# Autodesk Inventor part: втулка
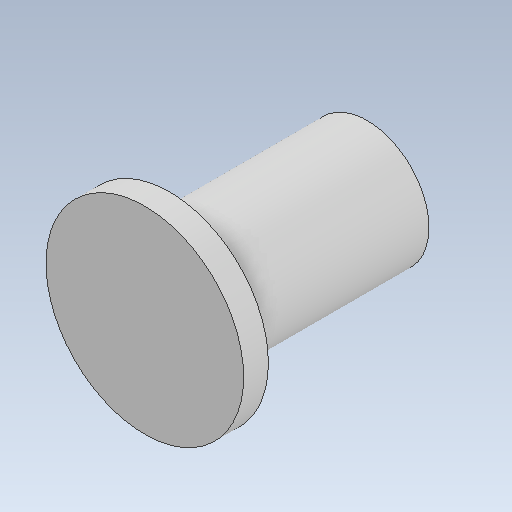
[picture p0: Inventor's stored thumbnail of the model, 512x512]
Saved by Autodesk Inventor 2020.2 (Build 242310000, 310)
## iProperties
Created: 2020-04
Part Number: втулка
Material: Типовые
Document SubType Name: Modeling
Designer: Алексей
Density: 1 g/cm^3
Appearance: По умолчанию
Author: Алексей
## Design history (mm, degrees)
sketch "Эскиз1"
  geometry: C1 r 2.5 at (-8.843, 5.951) reference; C2 r 2.5 at (-8.843, 5.951); 1 further point
  constraints: 1 centre point, 1 coincident
  dimensions: "d0" = 5 diameter of C2
extrude "Выдавливание1" new body sketch "Эскиз1" distance "d1" = 8; taper "d2" = 0 deg
sketch "Эскиз2"
  geometry: C1 r 4 at (0, 0); 1 further point
  constraints: 1 centre point
  dimensions: "d3" = 8 diameter of C1
extrude "Выдавливание2" join sketch "Эскиз2" distance "d4" = 1; taper "d5" = 0 deg
sketch "Эскиз3"
  geometry: C1 r 1.4 at (0, 0); 1 further point
  constraints: 1 centre point
  dimensions: "d6" = 2.8 diameter of C1
extrude "Выдавливание3" cut sketch "Эскиз3" distance "d7" = 8; taper "d8" = 0 deg
node "Твердое тело1"
node "Ссылка1"
